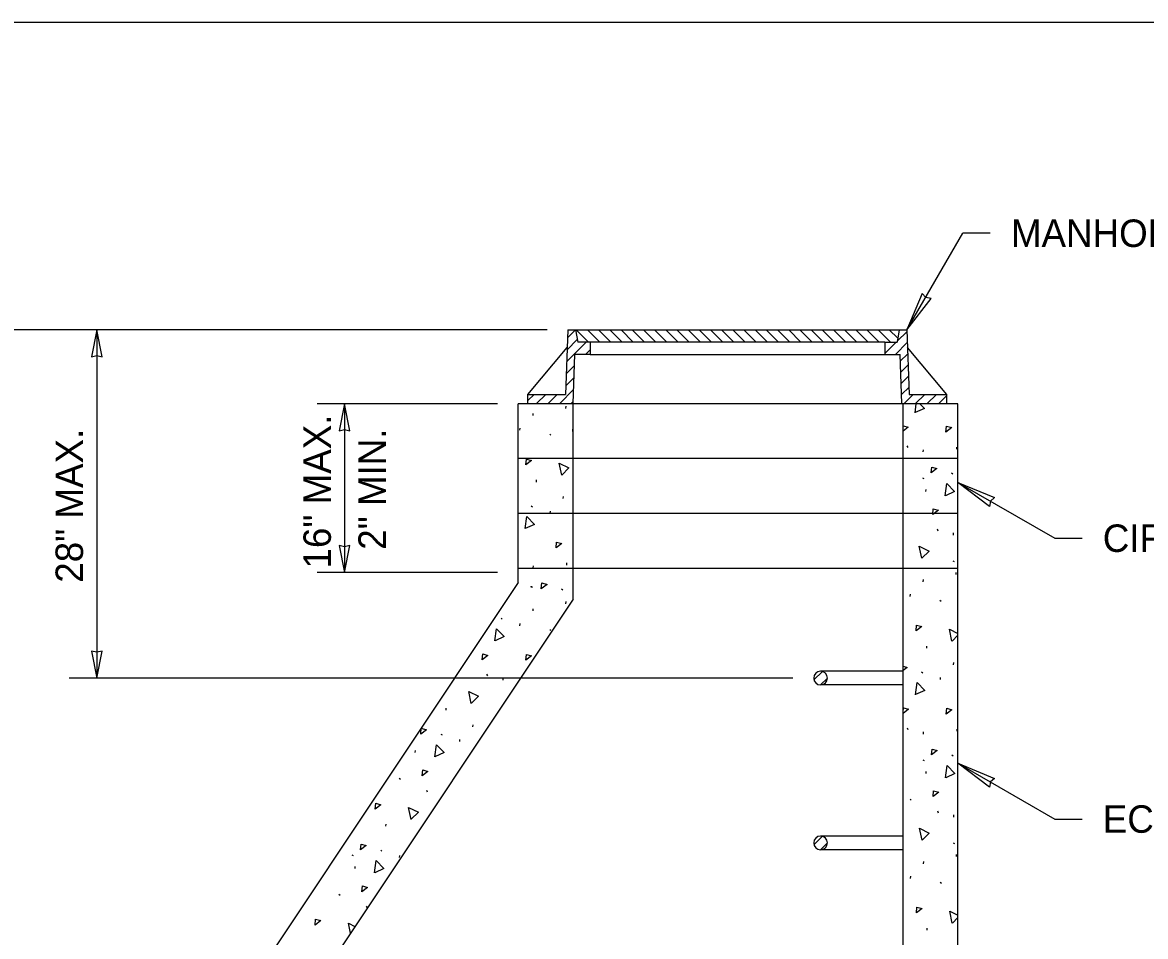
# Model space of a CAD drawing. Extents: x 99862 to 104211, y 98939 to 102076.
# Drawn here: x 100717 to 101370, y 101543 to 102076 of the extents above; entities that cross this region are included whole.
import ezdxf

# ---------------------------------------------------------------- set-up
doc = ezdxf.new("R2010")
doc.units = 0
for name, color, linetype in [('Level 1', 7, 'Continuous'), ('Level 15', 7, 'Continuous'), ('Level 17', 7, 'Continuous'), ('Level 18', 7, 'Continuous'), ('Level 19', 7, 'Continuous'), ('Level 20', 7, 'Continuous')]:
    doc.layers.add(name, color=color, linetype=linetype)

msp = doc.modelspace()

# ---------------------------------------------------------------- linework, layer by layer
at = {"layer": 'Level 1'}
msp.add_lwpolyline([(99862, 99999.5), (103151, 99999.5), (103151, 102075.5), (99862, 102075.5)], close=True, dxfattribs=at)
at = {"layer": 'Level 15'}
for p, q in [((101231.53, 101896.49), (101264.03, 101952.78)), ((101280.03, 101952.78), (101264.03, 101952.78)), ((101022.13, 101896.49), (100554.37, 101896.49)), ((100759.87, 101896.49), (100759.87, 101693.79)), ((100993.22, 101853.53), (100888.16, 101853.53)), ((100904.16, 101853.53), (100904.16, 101755.24)), ((101261.22, 101807.71), (101317.51, 101775.21)), ((101317.51, 101775.21), (101333.51, 101775.21)), ((100993.22, 101755.24), (100888.16, 101755.24)), ((101165.07, 101693.79), (100743.87, 101693.79)), ((101261.22, 101644.18), (101317.51, 101611.68)), ((101317.51, 101611.68), (101333.51, 101611.68))]:
    msp.add_line(p, q, dxfattribs=at)
for points in [[(101231.53, 101896.49), (101245.53, 101914.77), (101242.41, 101915.35), (101240.36, 101917.75)], [(100759.87, 101896.49), (100756.78, 101880.76), (100759.87, 101881.49), (100762.95, 101880.76)], [(100904.16, 101853.53), (100901.07, 101837.8), (100904.16, 101838.53), (100907.24, 101837.8)], [(101261.22, 101807.71), (101282.48, 101798.88), (101280.08, 101796.82), (101279.5, 101793.71)], [(100904.16, 101755.24), (100907.24, 101770.96), (100904.16, 101770.24), (100901.07, 101770.96)], [(100759.87, 101693.79), (100762.95, 101709.51), (100759.87, 101708.79), (100756.78, 101709.51)], [(101261.22, 101644.18), (101282.48, 101635.35), (101280.08, 101633.29), (101279.5, 101630.18)]]:
    msp.add_lwpolyline(points, close=True, dxfattribs=at)
at = {"layer": 'Level 17'}
for p, q in [((101005.22, 101749.47), (101005.22, 101853.53)), ((101037.22, 101853.53), (101005.22, 101853.53)), ((101037.22, 101739.79), (101037.22, 101853.53)), ((101261.22, 101853.53), (101229.22, 101853.53)), ((101229.22, 100299.79), (101229.22, 101853.53)), ((101261.22, 100251.79), (101261.22, 101853.53)), ((101037.22, 101821.53), (101005.22, 101821.53)), ((101229.22, 101821.53), (101037.22, 101821.53)), ((101261.22, 101821.53), (101229.22, 101821.53)), ((101037.22, 101789.53), (101005.22, 101789.53)), ((101229.22, 101789.53), (101037.22, 101789.53)), ((101261.22, 101789.53), (101229.22, 101789.53)), ((101037.22, 101757.53), (101005.22, 101757.53)), ((101229.22, 101757.53), (101037.22, 101757.53)), ((101261.22, 101757.53), (101229.22, 101757.53)), ((101005.22, 101749.47), (100813.22, 101461.47)), ((101037.22, 101739.79), (100845.22, 101451.79))]:
    msp.add_line(p, q, dxfattribs=at)
at = {"layer": 'Level 18'}
for p, q in [((101034.13, 101896.49), (101032.76, 101858.92)), ((101033.92, 101891.88), (101038.5, 101896.49)), ((101034.13, 101896.49), (101039.87, 101896.49)), ((101038.55, 101896.49), (101039.87, 101889.33)), ((101039.02, 101896.49), (101046.18, 101889.33)), ((101039.87, 101896.49), (101227.01, 101896.49)), ((101045.53, 101896.49), (101052.69, 101889.33)), ((101052.04, 101896.49), (101059.21, 101889.33)), ((101058.53, 101896.49), (101065.71, 101889.33)), ((101065.05, 101896.49), (101072.21, 101889.33)), ((101071.55, 101896.49), (101078.72, 101889.33)), ((101078.06, 101896.49), (101085.23, 101889.33)), ((101084.57, 101896.49), (101091.74, 101889.33)), ((101091.07, 101896.49), (101098.25, 101889.33)), ((101097.58, 101896.49), (101104.76, 101889.33)), ((101104.09, 101896.49), (101111.26, 101889.33)), ((101110.6, 101896.49), (101117.77, 101889.33)), ((101117.11, 101896.49), (101124.28, 101889.33)), ((101123.63, 101896.49), (101130.78, 101889.33)), ((101130.12, 101896.49), (101137.29, 101889.33)), ((101136.63, 101896.49), (101143.79, 101889.33)), ((101143.14, 101896.49), (101150.31, 101889.33)), ((101149.64, 101896.49), (101156.81, 101889.33)), ((101156.17, 101896.49), (101163.32, 101889.33)), ((101162.66, 101896.49), (101169.83, 101889.33)), ((101169.17, 101896.49), (101176.33, 101889.33)), ((101175.69, 101896.49), (101182.84, 101889.33)), ((101182.18, 101896.49), (101189.35, 101889.33)), ((101188.7, 101896.49), (101195.87, 101889.33)), ((101195.2, 101896.49), (101202.37, 101889.33)), ((101201.71, 101896.49), (101208.87, 101889.33)), ((101208.23, 101896.49), (101215.38, 101889.33)), ((101214.72, 101896.49), (101221.89, 101889.33)), ((101221.24, 101896.49), (101226.14, 101891.59)), ((101227.01, 101896.49), (101225.73, 101889.33)), ((101225.78, 101889.92), (101231.56, 101895.65)), ((101227.01, 101896.49), (101231.53, 101896.49)), ((101231.53, 101896.49), (101232.79, 101858.92)), ((101033.4, 101877.88), (101044.83, 101889.33)), ((101033.63, 101884.91), (101039.58, 101890.85)), ((101047.1, 101889.33), (101039.87, 101889.33)), ((101047.1, 101889.33), (101047.1, 101882.21)), ((101218.56, 101889.33), (101047.1, 101889.33)), ((101218.56, 101889.33), (101225.73, 101889.33)), ((101218.56, 101889.33), (101218.56, 101882.21)), ((101218.56, 101882.69), (101225.18, 101889.33)), ((101224.8, 101882.21), (101231.73, 101889.18)), ((101010.85, 101858.92), (101033.7, 101886.23)), ((101037.23, 101853.58), (101038.26, 101882.21)), ((101047.19, 101882.21), (101038.26, 101882.21)), ((101044.41, 101882.21), (101047.1, 101884.8)), ((101047.1, 101882.21), (101218.56, 101882.21)), ((101218.56, 101882.21), (101227.55, 101882.21)), ((101228.58, 101853.58), (101227.55, 101882.21)), ((101227.64, 101878.32), (101231.96, 101882.61)), ((101254.71, 101858.92), (101231.81, 101886.23)), ((101033.15, 101870.95), (101038.01, 101875.76)), ((101227.88, 101871.84), (101232.21, 101876.11)), ((101032.95, 101863.97), (101037.77, 101868.8)), ((101228.08, 101865.32), (101232.46, 101869.64)), ((101029.38, 101853.58), (101037.48, 101861.83)), ((101228.33, 101858.87), (101232.71, 101863.1)), ((101010.85, 101858.92), (101032.76, 101858.92)), ((101010.85, 101853.58), (101010.85, 101858.92)), ((101010.85, 101855.38), (101014.48, 101858.92)), ((101015.8, 101853.58), (101021.21, 101858.92)), ((101022.6, 101853.58), (101027.94, 101858.92)), ((101036.04, 101853.58), (101037.23, 101854.81)), ((101229.85, 101853.58), (101235.21, 101858.92)), ((101232.79, 101858.92), (101254.71, 101858.92)), ((101236.57, 101853.58), (101241.93, 101858.92)), ((101243.36, 101853.58), (101248.7, 101858.92)), ((101250.05, 101853.58), (101254.71, 101858.23)), ((101254.71, 101853.58), (101254.71, 101858.92)), ((101010.85, 101853.58), (101037.23, 101853.58)), ((101037.23, 101853.58), (101228.58, 101853.58)), ((101228.58, 101853.58), (101254.71, 101853.58)), ((101177.38, 101692.66), (101182.36, 101697.62)), ((101181.21, 101689.79), (101185.21, 101693.78)), ((101229.22, 101697.79), (101181.22, 101697.79)), ((101229.22, 101689.79), (101181.22, 101689.79)), ((101177.38, 101596.66), (101182.36, 101601.62)), ((101229.22, 101601.79), (101181.22, 101601.79)), ((101181.21, 101593.79), (101185.21, 101597.78)), ((101229.22, 101593.79), (101181.22, 101593.79))]:
    msp.add_line(p, q, dxfattribs=at)
for centre in [(101181.21, 101693.79), (101181.21, 101597.79)]:
    msp.add_arc(centre, 4, 270, 269.93001, dxfattribs=at)
at = {"layer": 'Level 19'}
for p, q in [((101032.94, 101850.78), (101033.03, 101852)), ((101013.83, 101846.59), (101013.91, 101847.81)), ((101006.23, 101838.02), (101006.31, 101839.24)), ((101023.55, 101835.85), (101024.28, 101835.33)), ((101231.44, 101828.95), (101231.94, 101827.94)), ((101240.98, 101825.4), (101241.07, 101826.62)), ((101260.48, 101827.07), (101260.57, 101828.3)), ((101015.86, 101807.92), (101015.95, 101809.14)), ((101240.62, 101810.45), (101241.34, 101809.92)), ((101257.44, 101813.21), (101258.16, 101812.68)), ((101242.54, 101802.43), (101242.62, 101803.66)), ((101031.42, 101798.24), (101031.51, 101799.46)), ((101012.82, 101794.05), (101013.54, 101793.52)), ((101023.83, 101789.67), (101023.91, 101790.89)), ((101249.04, 101780.6), (101249.54, 101779.59)), ((101258.58, 101777.05), (101258.67, 101778.27)), ((101013.96, 101757.9), (101014.04, 101759.12)), ((101033.46, 101759.57), (101033.55, 101760.79)), ((101258.22, 101762.1), (101258.94, 101761.57)), ((101241.02, 101749.89), (101241.11, 101751.11)), ((101260.13, 101754.08), (101260.22, 101755.31)), ((101030.41, 101745.7), (101031.13, 101745.17)), ((101032.94, 101737.04), (101033.03, 101738.26)), ((101233.43, 101741.32), (101233.51, 101742.54)), ((101250.75, 101739.16), (101251.47, 101738.63)), ((101013.83, 101732.85), (101013.91, 101734.07)), ((100995.22, 101728.66), (100995.94, 101728.13)), ((101006.23, 101724.28), (101006.31, 101725.5)), ((101023.55, 101722.11), (101024.28, 101721.59)), ((101243.06, 101711.22), (101243.14, 101712.44)), ((101258.62, 101701.54), (101258.71, 101702.76)), ((100986.82, 101696.06), (100987.32, 101695.05)), ((100996.36, 101692.5), (100996.45, 101693.73)), ((101240.01, 101697.35), (101240.73, 101696.83)), ((101251.02, 101692.97), (101251.11, 101694.19)), ((100963.24, 101675.03), (100963.33, 101676.25)), ((100978.8, 101665.34), (100978.89, 101666.57)), ((100960.19, 101661.16), (100960.91, 101660.63)), ((101231.61, 101664.75), (101232.11, 101663.74)), ((101241.15, 101661.2), (101241.24, 101662.42)), ((101260.65, 101662.87), (101260.74, 101664.09)), ((100971.21, 101656.77), (100971.29, 101658)), ((100945.29, 101650.39), (100945.38, 101651.61)), ((101240.79, 101646.25), (101241.51, 101645.72)), ((101257.61, 101649.01), (101258.33, 101648.48)), ((101242.71, 101638.23), (101242.79, 101639.45)), ((100935.91, 101635.46), (100936.63, 101634.93)), ((100951.8, 101628.55), (100952.29, 101627.54)), ((100961.41, 101626.08), (100961.42, 101626.22)), ((101233.32, 101623.31), (101234.04, 101622.78)), ((101249.21, 101616.4), (101249.71, 101615.39)), ((101258.75, 101612.85), (101258.84, 101614.07)), ((100928.21, 101607.52), (100928.3, 101608.75)), ((100925.17, 101593.66), (100925.89, 101593.13)), ((101258.39, 101597.9), (101259.11, 101597.37)), ((100908.35, 101590.9), (100909.07, 101590.37)), ((100936.18, 101589.27), (100936.26, 101590.49)), ((101241.19, 101585.69), (101241.28, 101586.91)), ((101260.31, 101589.88), (101260.39, 101591.11)), ((100910.27, 101582.88), (100910.35, 101584.11)), ((101233.6, 101577.12), (101233.68, 101578.34)), ((101250.92, 101574.96), (101251.64, 101574.43)), ((100900.88, 101567.96), (100901.6, 101567.43)), ((100916.77, 101561.05), (100917.27, 101560.04)), ((101243.23, 101547.02), (101243.31, 101548.24))]:
    msp.add_line(p, q, dxfattribs=at)
for points in [[(101236.23, 101848.28), (101236.96, 101853.53)], [(101239.01, 101853.53), (101241.67, 101850.79), (101236.34, 101848.32)], [(101036.93, 101837.28), (101037.22, 101840.24)], [(101037.22, 101837.5), (101036.93, 101837.28)], [(101229.22, 101840.24), (101229.26, 101840.71), (101232.24, 101839.81), (101229.22, 101837.5)], [(101254.24, 101837.04), (101254.58, 101840.47), (101257.55, 101839.57), (101254.24, 101837.04)], [(101009.62, 101817.88), (101009.96, 101821.31), (101012.93, 101820.41), (101009.62, 101817.88)], [(101030.51, 101811.88), (101029.01, 101818.9), (101034.77, 101816.1), (101030.61, 101811.96)], [(101245.68, 101813.22), (101246.02, 101816.65), (101249, 101815.75), (101245.68, 101813.22)], [(101253.83, 101799.93), (101254.81, 101807.03), (101259.26, 101802.44), (101253.94, 101799.97)], [(101246.53, 101788.93), (101246.86, 101792.36), (101249.84, 101791.46), (101246.53, 101788.93)], [(101009.2, 101780.78), (101010.19, 101787.88), (101014.64, 101783.28), (101009.32, 101780.82)], [(101027.21, 101769.53), (101027.55, 101772.97), (101030.52, 101772.06), (101027.21, 101769.53)], [(101240.11, 101763.54), (101238.61, 101770.55), (101244.37, 101767.75), (101240.21, 101763.61)], [(101012.91, 101746.49), (101012.77, 101747.19)], [(101013.43, 101746.99), (101013.01, 101746.57)], [(101018.66, 101745.72), (101019, 101749.15), (101021.97, 101748.25), (101018.66, 101745.72)], [(101236.81, 101721.19), (101237.15, 101724.62), (101240.12, 101723.71), (101236.81, 101721.19)], [(100991.61, 101715.39), (100992.59, 101722.49), (100997.04, 101717.89), (100991.72, 101715.43)], [(101257.71, 101715.19), (101256.21, 101722.2), (101261.22, 101719.76)], [(101261.22, 101718.66), (101257.81, 101715.27)], [(100984.31, 101704.39), (100984.64, 101707.82), (100987.62, 101706.92), (100984.31, 101704.39)], [(101009.62, 101704.14), (101009.96, 101707.57), (101012.93, 101706.67), (101009.62, 101704.14)], [(101229.22, 101700.61), (101231.57, 101699.9), (101229.22, 101698.1)], [(100977.89, 101678.99), (100976.39, 101686.01), (100982.15, 101683.21), (100977.99, 101679.07)], [(101236.4, 101684.08), (101237.38, 101691.18), (101241.84, 101686.59), (101236.51, 101684.12)], [(101229.22, 101674.3), (101229.43, 101676.51), (101232.41, 101675.61), (101229.22, 101673.17)], [(101254.41, 101672.84), (101254.75, 101676.27), (101257.72, 101675.37), (101254.41, 101672.84)], [(100948.44, 101661.17), (100948.78, 101664.6), (100951.75, 101663.7), (100948.44, 101661.17)], [(100956.58, 101647.88), (100957.57, 101654.99), (100962.02, 101650.39), (100956.7, 101647.93)], [(101245.85, 101649.02), (101246.19, 101652.45), (101249.17, 101651.55), (101245.85, 101649.02)], [(100949.28, 101636.89), (100949.62, 101640.32), (100952.59, 101639.42), (100949.28, 101636.89)], [(101254, 101635.73), (101254.98, 101642.83), (101259.43, 101638.24), (101254.11, 101635.77)], [(101246.7, 101624.73), (101247.03, 101628.16), (101250.01, 101627.26), (101246.7, 101624.73)], [(100921.97, 101617.49), (100922.31, 101620.92), (100925.28, 101620.02), (100921.97, 101617.49)], [(100942.86, 101611.49), (100941.36, 101618.5), (100947.12, 101615.7), (100942.96, 101611.57)], [(101240.28, 101599.34), (101238.78, 101606.35), (101244.54, 101603.55), (101240.38, 101599.41)], [(100913.41, 101593.67), (100913.75, 101597.1), (100916.73, 101596.2), (100913.41, 101593.67)], [(100921.56, 101580.38), (100922.54, 101587.48), (100926.99, 101582.89), (100921.67, 101580.42)], [(100914.26, 101569.39), (100914.59, 101572.82), (100917.57, 101571.91), (100914.26, 101569.39)], [(101236.98, 101556.99), (101237.32, 101560.42), (101240.29, 101559.51), (101236.98, 101556.99)], [(101257.88, 101550.99), (101256.38, 101558), (101261.22, 101555.65)], [(101261.22, 101554.29), (101257.98, 101551.07)], [(100886.94, 101549.99), (100887.28, 101553.42), (100890.25, 101552.52), (100886.94, 101549.99)], [(100907.56, 101545.3), (100906.34, 101551), (100910.13, 101549.16)]]:
    msp.add_lwpolyline(points, dxfattribs=at)

# ---------------------------------------------------------------- texts
at = {"layer": 'Level 20'}
for s, p in [('MANHOLE RING AND COVER', (101292.03, 101944.78)), ('CIRCULAR ADJUSTMENT SECTION (TYP.)', (101345.51, 101767.21)), ('ECCENTRIC CONE SECTION', (101345.51, 101603.68))]:
    msp.add_text(s, height=16, dxfattribs=at).set_placement(p)
for s, p in [('16" MAX.', (100896.16, 101757.56)), ('28" MAX.', (100751.87, 101749.29)), ('2" MIN.', (100928.16, 101768.48))]:
    msp.add_text(s, height=16, rotation=90, dxfattribs=at).set_placement(p)

doc.saveas('drawing.dxf')
